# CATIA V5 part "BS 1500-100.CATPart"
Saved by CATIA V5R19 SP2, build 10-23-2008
Part number: BS 1500-100
Bounding box of the stored display mesh (mm): x -31.459 to 31.459, y -31.459 to 31.459, z 0 to 244
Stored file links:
  C:\Users\Bora\Desktop\3D Katı model\BS serisi\BS 1500\BS 1500-100.CATPart
  C:\Program Files\Dassault Systemes\B19\intel_a\reffiles\standard\MetricThickPitch.txt
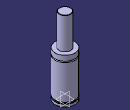
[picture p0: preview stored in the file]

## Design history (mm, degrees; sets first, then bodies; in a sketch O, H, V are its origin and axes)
Body1 (main body)
  Sketch1 on yz-plane, origin (0, 0, 0), H (0, 1, 0), V (0, 0, 1)
    point P1 (31.5, 127)
    point P2 (31.5, 123)
    point P3 (31.5, 127)
    point P7 (18, 243)
    point P9 (18, 243)
    point P14 (31.5, 123)
    arc A1 centre (31.5, 125) radius 2 from (31.5, 127) to (31.5, 123) ccw
    line L1 (31.5, 127) -> (31.5, 143)
    line L2 (31.5, 0) -> (31.5, 8)
    arc A2 centre (17, 243) radius 1 from (18, 243) to (17, 244) ccw
    line L3 (18, 243) -> (18, 143)
    line L4 (29, 13) -> (29, 8)
    line L5 (31.5, 13) -> (31.5, 123)
    line L6 (17, 244) -> (0, 244)
    line L7 (18, 143) -> (31.5, 143)
    line L8 (0, 0) -> (31.5, 0)
    line L9 (29, 8) -> (31.5, 8)
    line L10 (29, 13) -> (31.5, 13)
    tangency: L6 A2
    horizontal: L7 H, L8 H, L9 H, L10 H
    coincidence: P1 P3, P2 P14, P7 P9
  Shaft1: profile Sketch1, axis Sketch1.V, angle 360
  Sketch2 on face of Shaft1 from Sketch1.L8, origin (0, 0, 0), H (1, 0, 0), V (0, -1, 0)
    point P1 (10, 0)
    distance P1 V = 10
  Hole1: placed by Sketch2, at (10, 0, 0) direction (0, 0, 1), diameter 6.647, depth 5, threaded "M8", thread diameter 8, thread depth 5, pitch 1.25
  CircPattern1: of Hole1, instances 2, angular step 180, axis from face of Shaft1 from Sketch1.L8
